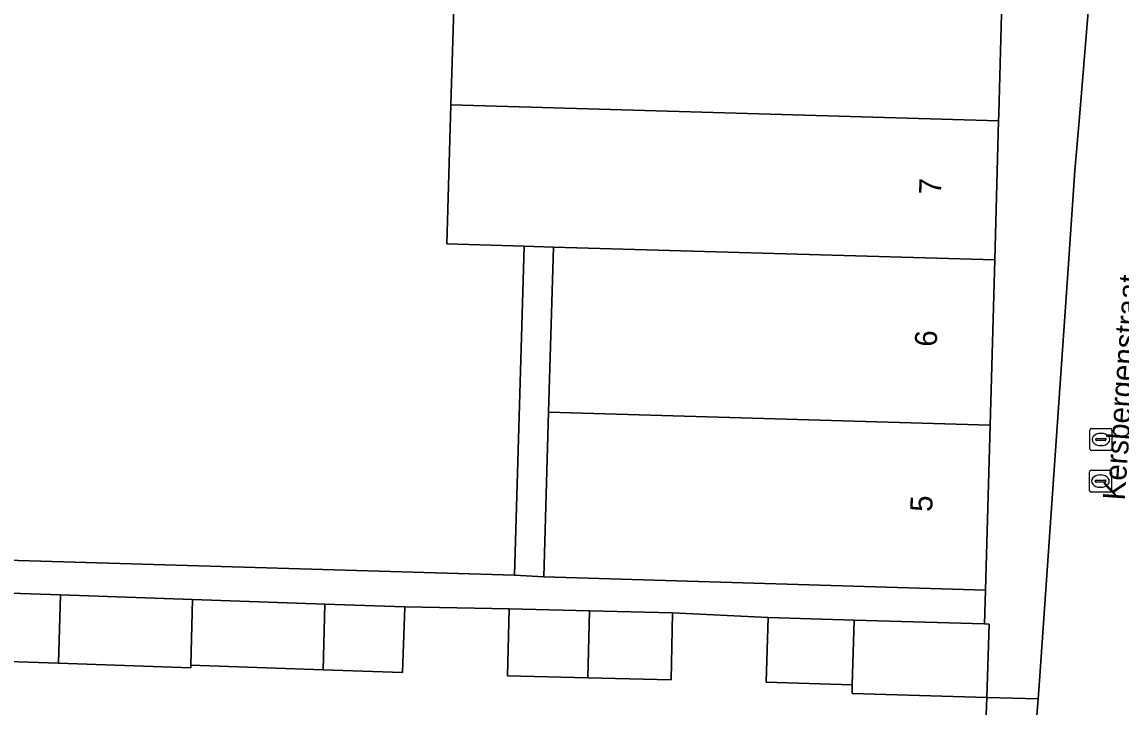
# Model space of a CAD drawing. Extents: x 159053 to 160042, y 380449 to 381423.
# Drawn here: x 159368.83 to 159418.74, y 381214.54 to 381245.66 of the extents above; entities that cross this region are included whole.
import ezdxf

# ---------------------------------------------------------------- set-up
doc = ezdxf.new("R2010")
doc.units = 0
for name, color, linetype in [('IMGEO_Berm_groen', 7, 'Continuous'), ('IMGEO_Erf', 7, 'Continuous'), ('IMGEO_Kolk', 7, 'Continuous'), ('IMGEO_Openbare_ruimte_label', 7, 'Continuous'), ('IMGEO_Pand', 7, 'Continuous'), ('IMGEO_Pand_nummerreeks', 7, 'Continuous'), ('IMGEO_Rijbaan_lokaal_open', 7, 'Continuous'), ('IMGEO_Rioolput', 7, 'Continuous'), ('IMGEO_Voetpad_open', 7, 'Continuous')]:
    doc.layers.add(name, color=color, linetype=linetype)

msp = doc.modelspace()

# ---------------------------------------------------------------- linework, layer by layer
at = {"layer": 'IMGEO_Berm_groen'}
msp.add_lwpolyline([(159414.538, 381209.296), (159414.752, 381212.087), (159414.968, 381214.908), (159412.643, 381214.977), (159412.342, 381207.116), (159412.123, 381199.079), (159413.749, 381198.987)], close=True, dxfattribs=at)
at = {"layer": 'IMGEO_Erf'}
msp.add_lwpolyline([(159392.963, 381235.433), (159391.636, 381235.472), (159391.193, 381220.523), (159392.519, 381220.449), (159392.741, 381227.941)], close=True, dxfattribs=at)
msp.add_lwpolyline([(159412.342, 381207.116), (159412.643, 381214.977), (159406.524, 381215.158), (159406.534, 381215.548), (159402.62, 381215.664), (159402.707, 381218.605), (159398.375, 381218.822), (159398.303, 381215.773), (159394.519, 381215.863), (159390.883, 381215.949), (159390.955, 381218.998), (159386.216, 381219.088), (159386.111, 381216.102), (159382.502, 381216.23), (159376.498, 381216.442), (159376.495, 381216.314), (159370.488, 381216.525), (159366.828, 381216.653)], dxfattribs=at)
at = {"layer": 'IMGEO_Kolk'}
for p, q in [((159417.325, 381226.266), (159417.325, 381227.118)), ((159417.4, 381227.192), (159418.252, 381227.192)), ((159417.813, 381226.972), (159417.838, 381226.972)), ((159418.326, 381227.118), (159418.326, 381226.266)), ((159417.584, 381226.686), (159417.584, 381226.698)), ((159418.022, 381226.649), (159417.624, 381226.649)), ((159417.627, 381226.735), (159418.025, 381226.735)), ((159418.068, 381226.698), (159418.068, 381226.686)), ((159418.252, 381226.192), (159417.4, 381226.192)), ((159417.836, 381226.412), (159417.811, 381226.412))]:
    msp.add_line(p, q, dxfattribs=at)
for points in [[(159417.325, 381226.266), (159417.325, 381227.118)], [(159417.4, 381227.192), (159418.252, 381227.192)], [(159418.326, 381227.118), (159418.326, 381226.266)], [(159418.252, 381226.192), (159417.4, 381226.192)]]:
    msp.add_lwpolyline(points, dxfattribs=at)
for centre, radius, start, end in [((159417.402, 381227.116), 0.0765, 91.552, 178.448), ((159417.402, 381227.116), 0.0765, 91.552, 178.448), ((159418.25, 381227.116), 0.0765, 1.552, 88.448), ((159418.25, 381227.116), 0.0765, 1.552, 88.448), ((159417.624, 381226.695), 0.0403, 85.8775, 175.7526), ((159417.621, 381226.685), 0.0366, 178.938, 274.7102), ((159418.025, 381226.692), 0.043, 264.8664, 352.4533), ((159418.029, 381226.697), 0.0386, 1.7309, 96.639), ((159417.402, 381226.268), 0.0765, 181.552, 268.448), ((159417.402, 381226.268), 0.0765, 181.552, 268.448), ((159418.25, 381226.268), 0.0765, 271.552, 358.448), ((159418.25, 381226.268), 0.0765, 271.552, 358.448)]:
    msp.add_arc(centre, radius, start, end, dxfattribs=at)
for centre, major_axis, ratio, start_param, end_param in [((159417.812, 381226.692), (-0.387, 0.002), 0.722429, 4.712389, 7.853982), ((159417.837, 381226.692), (-0.39, 0.002), 0.717154, 1.570796, 4.712389)]:
    msp.add_ellipse(centre, major_axis=major_axis, ratio=ratio, start_param=start_param, end_param=end_param, dxfattribs=at)
at = {"layer": 'IMGEO_Pand'}
for points in [[(159388.306, 381241.899), (159413.175, 381241.164), (159413.184, 381241.507), (159413.419, 381250), (159413.435, 381250.58), (159407.312, 381250.751), (159407.3, 381250), (159407.292, 381249.501), (159405.259, 381249.561), (159405.205, 381247.729), (159388.493, 381248.223)], [(159388.306, 381241.899), (159388.493, 381248.223), (159388.551, 381250), (159388.557, 381250.19), (159387.584, 381250), (159385.535, 381249.6), (159378.574, 381248.24), (159373.269, 381247.204), (159367.16, 381246.011), (159360.41, 381244.692), (159353.523, 381243.347), (159344.026, 381241.492), (159343.33, 381241.356), (159342.009, 381221.978), (159391.193, 381220.523), (159391.636, 381235.472), (159388.119, 381235.575)], [(159388.306, 381241.899), (159388.119, 381235.575), (159391.636, 381235.472), (159392.963, 381235.433), (159413.001, 381234.861), (159413.175, 381241.164)], [(159413.001, 381234.861), (159392.963, 381235.433), (159392.741, 381227.941), (159412.793, 381227.347)], [(159412.793, 381227.347), (159392.741, 381227.941), (159392.519, 381220.449), (159407.589, 381220.003), (159412.586, 381219.855)], [(159370.571, 381219.635), (159366.937, 381219.762), (159366.828, 381216.653), (159370.488, 381216.525)], [(159376.578, 381219.425), (159370.571, 381219.635), (159370.488, 381216.525), (159376.495, 381216.314), (159376.498, 381216.442)], [(159382.581, 381219.215), (159376.578, 381219.425), (159376.498, 381216.442), (159382.502, 381216.23)], [(159386.216, 381219.088), (159382.581, 381219.215), (159382.502, 381216.23), (159386.111, 381216.102)], [(159394.519, 381215.863), (159394.6, 381218.912), (159390.955, 381218.998), (159390.883, 381215.949)], [(159394.519, 381215.863), (159398.303, 381215.773), (159398.375, 381218.822), (159394.6, 381218.912)], [(159406.613, 381218.489), (159402.707, 381218.605), (159402.62, 381215.664), (159406.534, 381215.548)], [(159412.742, 381218.308), (159412.543, 381218.314), (159406.613, 381218.489), (159406.534, 381215.548), (159406.524, 381215.158), (159412.643, 381214.977)]]:
    msp.add_lwpolyline(points, close=True, dxfattribs=at)
at = {"layer": 'IMGEO_Rijbaan_lokaal_open'}
msp.add_lwpolyline([(159418.719, 381267.127), (159418.471, 381262.899), (159418.138, 381256.93), (159417.564, 381250), (159416.846, 381241.338), (159416.645, 381238.911), (159416.349, 381234.665), (159414.999, 381215.304), (159414.968, 381214.908), (159414.752, 381212.087), (159419.735, 381211.721)], dxfattribs=at)
at = {"layer": 'IMGEO_Rioolput'}
for p, q in [((159417.302, 381224.377), (159417.302, 381225.229)), ((159417.377, 381225.303), (159418.229, 381225.303)), ((159417.79, 381225.083), (159417.815, 381225.083)), ((159418.303, 381225.229), (159418.303, 381224.377)), ((159417.561, 381224.797), (159417.561, 381224.809)), ((159417.999, 381224.76), (159417.601, 381224.76)), ((159417.604, 381224.846), (159418.002, 381224.846)), ((159417.813, 381224.523), (159417.788, 381224.523)), ((159418.045, 381224.809), (159418.045, 381224.797)), ((159418.229, 381224.303), (159417.377, 381224.303))]:
    msp.add_line(p, q, dxfattribs=at)
for points in [[(159417.302, 381224.377), (159417.302, 381225.229)], [(159417.377, 381225.303), (159418.229, 381225.303)], [(159418.303, 381225.229), (159418.303, 381224.377)], [(159418.229, 381224.303), (159417.377, 381224.303)]]:
    msp.add_lwpolyline(points, dxfattribs=at)
for centre, radius, start, end in [((159417.379, 381225.227), 0.0765, 91.552, 178.448), ((159417.379, 381225.227), 0.0765, 91.552, 178.448), ((159418.227, 381225.227), 0.0765, 1.552, 88.448), ((159418.227, 381225.227), 0.0765, 1.552, 88.448), ((159417.601, 381224.806), 0.0403, 85.8775, 175.7526), ((159417.598, 381224.796), 0.0366, 178.938, 274.7102), ((159418.002, 381224.803), 0.043, 264.8664, 352.4533), ((159418.006, 381224.808), 0.0386, 1.7309, 96.639), ((159417.379, 381224.379), 0.0765, 181.552, 268.448), ((159417.379, 381224.379), 0.0765, 181.552, 268.448), ((159418.227, 381224.379), 0.0765, 271.552, 358.448), ((159418.227, 381224.379), 0.0765, 271.552, 358.448)]:
    msp.add_arc(centre, radius, start, end, dxfattribs=at)
for centre, major_axis, ratio, start_param, end_param in [((159417.789, 381224.803), (-0.387, 0.002), 0.722429, 4.712389, 7.853982), ((159417.814, 381224.803), (-0.39, 0.002), 0.717154, 1.570796, 4.712389)]:
    msp.add_ellipse(centre, major_axis=major_axis, ratio=ratio, start_param=start_param, end_param=end_param, dxfattribs=at)
at = {"layer": 'IMGEO_Voetpad_open'}
msp.add_lwpolyline([(159413.419, 381250), (159413.184, 381241.507), (159413.175, 381241.164), (159413.001, 381234.861), (159412.793, 381227.347), (159412.586, 381219.855), (159412.543, 381218.314), (159412.742, 381218.308), (159412.643, 381214.977), (159414.968, 381214.908), (159414.999, 381215.304), (159416.349, 381234.665), (159416.645, 381238.911), (159416.846, 381241.338), (159417.564, 381250)], dxfattribs=at)
msp.add_lwpolyline([(159392.519, 381220.449), (159391.193, 381220.523), (159342.009, 381221.978), (159339.422, 381222.167), (159339.319, 381220.746), (159342.932, 381220.587), (159346.554, 381220.48), (159350.254, 381220.37), (159352.624, 381220.068), (159358.553, 381219.892), (159362.148, 381219.785), (159366.937, 381219.762), (159370.571, 381219.635), (159376.578, 381219.425), (159382.581, 381219.215), (159386.216, 381219.088), (159390.955, 381218.998), (159394.6, 381218.912), (159398.375, 381218.822), (159402.707, 381218.605), (159406.613, 381218.489), (159412.543, 381218.314), (159412.586, 381219.855), (159407.589, 381220.003)], close=True, dxfattribs=at)

# ---------------------------------------------------------------- texts
at = {"layer": 'IMGEO_Openbare_ruimte_label'}
msp.add_text('Kersbergenstraat', height=1, rotation=85.8695, dxfattribs=at).set_placement((159418.899, 381223.907))
at = {"layer": 'IMGEO_Pand_nummerreeks'}
for s, p in [('7', (159410.561, 381237.806)), ('6', (159410.37, 381230.898)), ('5', (159410.163, 381223.395))]:
    msp.add_text(s, height=1, rotation=88.4171, dxfattribs=at).set_placement(p)

doc.saveas('drawing.dxf')
